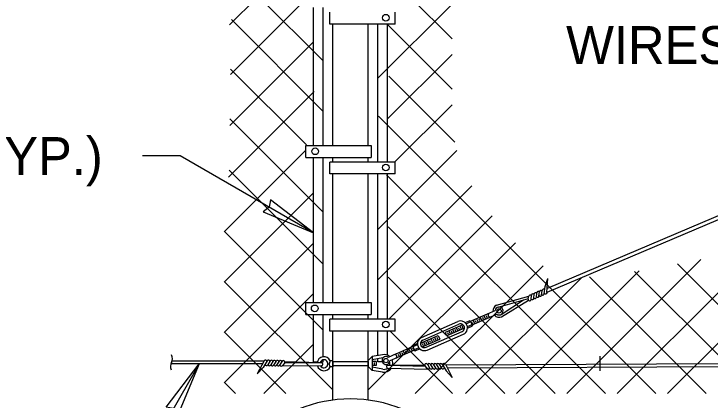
# Model space of a CAD drawing. Extents: x 99862 to 104211, y 98939 to 105076.
# Drawn here: x 100145.4 to 100439.3, y 101282.8 to 101445.9 of the extents above; entities that cross this region are included whole.
import ezdxf

# ---------------------------------------------------------------- set-up
doc = ezdxf.new("R2010")
doc.units = 0
for name, color, linetype in [('Level 15', 7, 'Continuous'), ('Level 2', 7, 'Continuous'), ('Level 20', 7, 'Continuous'), ('Level 4', 7, 'Continuous'), ('Level 6', 7, 'Continuous'), ('Level 7', 7, 'Continuous')]:
    doc.layers.add(name, color=color, linetype=linetype)

msp = doc.modelspace()

# ---------------------------------------------------------------- linework, layer by layer
at = {"layer": 'Level 15'}
for p, q in [((100215.65, 101385.93), (100199.65, 101385.93)), ((100271.94, 101353.42), (100215.65, 101385.92)), ((100223.62, 101298.08), (100191.25, 101242.02))]:
    msp.add_line(p, q, dxfattribs=at)
for points in [[(100271.94, 101353.43), (100253.66, 101367.43), (100253.09, 101364.31), (100250.68, 101362.26)], [(100223.62, 101298.08), (100214.79, 101276.82), (100212.73, 101279.23), (100209.62, 101279.8)]]:
    msp.add_lwpolyline(points, close=True, dxfattribs=at)
at = {"layer": 'Level 2'}
for p, q in [((100960.97, 101579.87), (100370.46, 101328.2)), ((100961.07, 101581.33), (100370.56, 101329.95)), ((100369.67, 101330.79), (100370.8, 101334.2)), ((100370.46, 101328.19), (100370.8, 101334.2)), ((100369.29, 101327.6), (100369.67, 101330.79)), ((100363.75, 101325.22), (100363.97, 101327.14)), ((100364.86, 101325.68), (100365.09, 101327.65)), ((100365.96, 101326.14), (100366.21, 101328.12)), ((100367.07, 101326.6), (100367.33, 101328.68)), ((100368.18, 101327.09), (100368.43, 101329.07)), ((100349.2, 101322.82), (100362.8, 101326.6)), ((100349.79, 101322.02), (100362.61, 101325.65)), ((100351.07, 101318.97), (100360.53, 101325.06)), ((100351.27, 101318), (100362.63, 101325.01)), ((100362.58, 101325.49), (100362.8, 101326.6)), ((100338.21, 101316.05), (100345.32, 101319.17)), ((100343.8, 101318.5), (100344.47, 101316.97)), ((100344.73, 101318.45), (100345.06, 101317.69)), ((100345.32, 101319.17), (100348.58, 101320.59)), ((100345.99, 101317.64), (100349.25, 101319.07)), ((100317.54, 101309.26), (100332.8, 101315.95)), ((100335.88, 101315.48), (100338.05, 101316.43)), ((100338.05, 101316.43), (100339.05, 101314.14)), ((100338.62, 101315.78), (100338.96, 101315.01)), ((100338.88, 101314.52), (100345.99, 101317.64)), ((100339.22, 101316.49), (100339.89, 101314.97)), ((100340.15, 101316.44), (100340.48, 101315.68)), ((100340.75, 101317.16), (100341.42, 101315.63)), ((100341.68, 101317.11), (100342.01, 101316.35)), ((100342.27, 101317.83), (100342.94, 101316.3)), ((100343.2, 101317.78), (100343.54, 101317.02)), ((100318.04, 101308.12), (100333.3, 101314.81)), ((100334.96, 101314.62), (100327.53, 101311.37)), ((100335.63, 101313.1), (100328.2, 101309.84)), ((100330.59, 101312.71), (100331.26, 101311.18)), ((100331.52, 101312.66), (100331.85, 101311.9)), ((100332.11, 101313.38), (100332.78, 101311.85)), ((100333.04, 101313.33), (100333.38, 101312.57)), ((100333.64, 101314.04), (100334.31, 101312.52)), ((100334.57, 101314), (100334.9, 101313.23)), ((100336.88, 101313.19), (100339.05, 101314.14)), ((100317.06, 101306.78), (100324.48, 101310.03)), ((100319.38, 101305.06), (100334.65, 101311.76)), ((100319.88, 101303.92), (100335.16, 101310.62)), ((100322.96, 101309.36), (100323.63, 101307.84)), ((100324.48, 101310.03), (100325.15, 101308.5)), ((100327.53, 101311.37), (100328.2, 101309.84)), ((100328.46, 101311.32), (100328.8, 101310.56)), ((100329.06, 101312.04), (100329.73, 101310.51)), ((100329.99, 101311.99), (100330.33, 101311.23)), ((100315.79, 101306.68), (100313.63, 101305.73)), ((100317.73, 101305.25), (100325.15, 101308.5)), ((100317.78, 101306.64), (100318.12, 101305.88)), ((100318.38, 101307.35), (100319.05, 101305.83)), ((100319.31, 101307.31), (100319.64, 101306.54)), ((100319.9, 101308.02), (100320.57, 101306.5)), ((100320.83, 101307.98), (100321.17, 101307.21)), ((100321.43, 101308.69), (100322.1, 101307.17)), ((100322.36, 101308.65), (100322.7, 101307.88)), ((100323.89, 101309.31), (100324.22, 101308.55)), ((100313.8, 101305.35), (100306.69, 101302.23)), ((100314.47, 101303.82), (100307.36, 101300.71)), ((100309.74, 101303.57), (100310.41, 101302.04)), ((100310.67, 101303.52), (100311.01, 101302.76)), ((100311.27, 101304.24), (100311.94, 101302.71)), ((100312.2, 101304.19), (100312.54, 101303.43)), ((100312.8, 101304.91), (100313.47, 101303.38)), ((100313.63, 101305.73), (100314.63, 101303.44)), ((100313.73, 101304.86), (100314.06, 101304.1)), ((100316.8, 101304.39), (100314.63, 101303.44)), ((100296.62, 101301.14), (100294.94, 101299.46)), ((100300.94, 101301.91), (100296.62, 101301.14)), ((100296.62, 101301.14), (100296.62, 101295.3)), ((100301.12, 101300.67), (100296.62, 101299.8)), ((100306.71, 101302.24), (100303.45, 101300.81)), ((100307.38, 101300.71), (100304.12, 101299.29)), ((100307.62, 101302.18), (100307.96, 101301.42)), ((100308.22, 101302.9), (100308.89, 101301.37)), ((100309.15, 101302.85), (100309.48, 101302.09)), ((100327.66, 101297.65), (100958.91, 101300.79)), ((100250.34, 101298.08), (100211.63, 101298.08)), ((100250.93, 101299.16), (100212.12, 101299.16)), ((100251.01, 101299.32), (100248.06, 101293.84)), ((100252.36, 101299.36), (100250.61, 101296.54)), ((100253.62, 101299.34), (100252.53, 101297.6)), ((100254.88, 101299.32), (100253.81, 101297.63)), ((100256.12, 101299.27), (100255.02, 101297.52)), ((100257.35, 101299.21), (100256.27, 101297.47)), ((100258.59, 101299.16), (100257.54, 101297.46)), ((100259.57, 101298.4), (100258.87, 101297.46)), ((100275.21, 101298.46), (100259.57, 101298.4)), ((100269.95, 101298.6), (100259.73, 101298.87)), ((100275.23, 101298.46), (100269.95, 101298.6)), ((100278.91, 101299.35), (100278.52, 101298.1)), ((100278.91, 101296.85), (100278.52, 101298.1)), ((100279.97, 101298.93), (100279.97, 101297.26)), ((100294.94, 101298.93), (100279.97, 101298.93)), ((100294.94, 101299.05), (100294.94, 101297.39)), ((100294.94, 101298.22), (100294.94, 101297.39)), ((100298.27, 101299.05), (100296.62, 101299.05)), ((100297.44, 101298.64), (100297.44, 101297.8)), ((100298.27, 101299.05), (100298.27, 101297.39)), ((100308.58, 101297.54), (100318.81, 101297.61)), ((100319.96, 101297.88), (100320.97, 101296.16)), ((100321.19, 101297.91), (100322.24, 101296.15)), ((100322.43, 101297.94), (100323.49, 101296.17)), ((100323.66, 101297.97), (100324.79, 101296.11)), ((100324.92, 101297.97), (100325.98, 101296.2)), ((100326.19, 101297.96), (100327.88, 101295.1)), ((100327.54, 101297.89), (100330.38, 101292.36)), ((100328.32, 101296.35), (100958.26, 101299.48)), ((100250.61, 101296.54), (100248.06, 101293.84)), ((100253.72, 101297.49), (100253.72, 101297.49)), ((100275.19, 101297.21), (100258.46, 101297.14)), ((100294.94, 101297.26), (100279.97, 101297.26)), ((100296.62, 101295.3), (100294.94, 101296.99)), ((100298.27, 101297.39), (100296.62, 101297.39)), ((100301.12, 101295.77), (100296.62, 101296.65)), ((100300.94, 101294.53), (100296.62, 101295.3)), ((100303.31, 101297.51), (100308.58, 101297.54)), ((100303.31, 101297.51), (100318.96, 101297.14)), ((100303.32, 101296.26), (100320.05, 101295.86)), ((100318.96, 101297.14), (100319.64, 101296.18)), ((100327.88, 101295.1), (100330.38, 101292.36))]:
    msp.add_line(p, q, dxfattribs=at)
for points in [[(100336.29, 101315.04), (100338.27, 101315.91)], [(100336.84, 101313.79), (100338.82, 101314.66)], [(100315.84, 101306.08), (100313.86, 101305.21)], [(100316.39, 101304.83), (100314.4, 101303.96)], [(100279.97, 101298.93), (100279.97, 101299.35), (100278.91, 101299.35)], [(100294.94, 101299.05), (100294.94, 101299.46)], [(100279.97, 101297.26), (100279.97, 101296.85), (100278.91, 101296.85)], [(100294.94, 101297.39), (100294.94, 101296.99)]]:
    msp.add_lwpolyline(points, dxfattribs=at)
for centre in [(100350.24, 101320.41), (100302.47, 101299.47)]:
    msp.add_circle(centre, 0.916, dxfattribs=at)
for centre, radius, start, end in [((100363.41, 101326.57), 0.605, 28.7661, 176.7144), ((100364.57, 101327.07), 0.605, 36.3421, 173.4693), ((100365.69, 101327.56), 0.605, 35.2689, 175.7258), ((100366.81, 101328.05), 0.605, 36.1699, 172.965), ((100367.59, 101327.24), 0.605, 216.0905, 359.5302), ((100367.92, 101328.53), 0.605, 36.7927, 180.322), ((100368.7, 101327.72), 0.605, 216.1693, 357.792), ((100369.03, 101329), 0.605, 38.1909, 172.8552), ((100369.86, 101328.22), 0.605, 209.8958, 356.7345), ((100363.15, 101325.31), 0.605, 162.4528, 355.3366), ((100364.26, 101325.79), 0.605, 216.3997, 357.0048), ((100365.37, 101326.27), 0.605, 216.3421, 359.0605), ((100366.48, 101326.76), 0.605, 216.2101, 0.322), ((100350.24, 101320.41), 2.63, 113.1749, 184.958), ((100350.24, 101320.41), 1.67, 233.6727, 173.6727), ((100346.44, 101318.75), 0.833, 113.6727, 293.6727), ((100350.24, 101320.41), 2.63, 222.1419, 293.1749), ((100333.97, 101313.28), 2.92, 37.2007, 113.6746), ((100333.97, 101313.28), 1.67, 53.6838, 113.6744), ((100333.97, 101313.28), 1.67, 293.6727, 53.6838), ((100333.97, 101313.28), 2.92, 293.6727, 37.2007), ((100318.71, 101306.59), 2.92, 113.6708, 190.1479), ((100318.71, 101306.59), 1.67, 173.6727, 293.6727), ((100318.71, 101306.59), 1.67, 113.6709, 173.6727), ((100318.71, 101306.59), 2.92, 189.6133, 293.6727), ((100209.12, 101300.26), 3.2, 330, 30), ((100276.27, 101298.1), 2.92, 25.3769, 172.7881), ((100302.47, 101299.47), 1.67, 53.6727, 353.6727), ((100301.6, 101298.22), 3.75, 49.4316, 100.1113), ((100301.6, 101298.22), 2.5, 95.7425, 101.0207), ((100306.26, 101301.13), 0.833, 293.6727, 113.6727), ((100214.66, 101297.06), 3.2, 150, 206.9934), ((100251.56, 101299.02), 0.625, 4.8632, 151.7019), ((100252, 101297.94), 0.625, 193.1646, 327.8289), ((100252.86, 101298.99), 0.625, 11.143, 143.5923), ((100253.24, 101297.89), 0.625, 191.7664, 335.2957), ((100254.11, 101298.95), 0.625, 154.3668, 154.5039), ((100254.11, 101298.95), 0.625, 11.0642, 141.1539), ((100254.49, 101297.86), 0.625, 191.1436, 327.9387), ((100255.36, 101298.92), 0.625, 11.1838, 139.9368), ((100255.76, 101297.82), 0.625, 190.2426, 325.8817), ((100256.61, 101298.89), 0.625, 153.8022, 154.0342), ((100256.61, 101298.89), 0.625, 11.3158, 141.8431), ((100257.01, 101297.79), 0.625, 191.3158, 328.443), ((100257.86, 101298.85), 0.625, 11.3734, 144.6027), ((100258.32, 101297.75), 0.625, 183.7398, 331.6881), ((100259.11, 101298.82), 0.625, 150.1377, 150.3103), ((100259.11, 101298.82), 0.625, 317.4265, 146.5757), ((100276.27, 101298.1), 1.67, 41.9482, 167.4497), ((100276.27, 101298.1), 1.67, 212.6493, 41.9482), ((100275.21, 101297.83), 0.625, 268.4659, 90.2119), ((100301.6, 101298.22), 2.5, 343.3732, 14.8434), ((100301.6, 101298.22), 3.75, 349.003, 23.1078), ((100319.43, 101297.55), 0.625, 28.5603, 221.4441), ((100320.68, 101297.56), 0.625, 26.8921, 167.4972), ((100321.93, 101297.57), 0.625, 24.8364, 167.5548), ((100323.18, 101297.58), 0.625, 23.5749, 167.6867), ((100324.43, 101297.59), 0.625, 24.3666, 167.8064), ((100325.68, 101297.59), 0.625, 26.1049, 167.7276), ((100326.98, 101297.6), 0.625, 27.1624, 174.0011), ((100276.27, 101298.1), 2.92, 198.7243, 334.6231), ((100301.6, 101298.22), 3.75, 259.8887, 327.5882), ((100301.6, 101298.22), 2.5, 258.8638, 308.7888), ((100303.31, 101296.88), 0.625, 90.4046, 270.4046), ((100320.2, 101296.47), 0.625, 207.1825, 355.1307), ((100321.51, 101296.48), 0.625, 210.4276, 347.5548), ((100322.76, 101296.49), 0.625, 208.1711, 348.628), ((100324.03, 101296.5), 0.625, 210.9319, 347.727), ((100325.28, 101296.51), 0.625, 203.5749, 347.1042), ((100326.52, 101296.53), 0.625, 211.0417, 345.706)]:
    msp.add_arc(centre, radius, start, end, dxfattribs=at)
at = {"layer": 'Level 4'}
for p, q in [((100236.47, 101441.29), (100271.77, 101476.59)), ((100275.96, 101426.04), (100235.97, 101466.03)), ((100330.41, 101435.42), (100303.25, 101462.57)), ((100236.84, 101420.38), (100269.94, 101453.48)), ((100299.03, 101418.73), (100330.41, 101450.1)), ((100275.96, 101404.75), (100237.19, 101443.53)), ((100330.41, 101414.14), (100303.08, 101441.47)), ((100236.52, 101398.79), (100271.77, 101434.03)), ((100302.96, 101401.41), (100330.41, 101428.84)), ((100268.9, 101390.54), (100236.88, 101422.55)), ((100331.55, 101391.72), (100303.62, 101419.65)), ((100235.99, 101377), (100272.13, 101413.13)), ((100306.24, 101383.38), (100330.41, 101407.55)), ((100275.96, 101362.2), (100236.57, 101401.59)), ((100416.43, 101285.55), (100299.34, 101402.66)), ((100234.15, 101353.85), (100268.66, 101388.36)), ((100299.03, 101354.9), (100332.39, 101388.26)), ((100275.96, 101340.13), (100236.22, 101379.87)), ((100395.16, 101285.55), (100302.73, 101377.98)), ((100299.03, 101333.63), (100338.71, 101373.3)), ((100234.15, 101332.64), (100271.56, 101370.03)), ((100303.67, 101316.98), (100347.3, 101360.61)), ((100275.96, 101312.37), (100234.17, 101354.16)), ((100373.88, 101285.55), (100303.41, 101356.02)), ((100421.38, 101285.55), (100486.76, 101350.93)), ((100234.15, 101311.3), (100271.89, 101349.03)), ((100295.02, 101287.05), (100357.17, 101349.19)), ((100400.1, 101285.55), (100461.82, 101347.27)), ((100378.82, 101285.55), (100435.46, 101342.19)), ((100314.79, 101285.55), (100368.8, 101339.55)), ((100480.27, 101285.55), (100425.56, 101340.26)), ((100357.55, 101285.55), (100409.4, 101337.41)), ((100459, 101285.55), (100407.44, 101337.11)), ((100279.97, 101287.08), (100234.15, 101332.9)), ((100352.61, 101285.55), (100303.43, 101334.72)), ((100336.1, 101285.55), (100385.14, 101334.59)), ((100437.72, 101285.55), (100388.46, 101334.8)), ((100234.15, 101290.02), (100271.93, 101327.8)), ((100260.23, 101285.55), (100234.15, 101311.63)), ((100330.54, 101285.55), (100304.13, 101311.96)), ((100250.95, 101285.55), (100271.84, 101306.44)), ((100392.77, 101301.3), (100392.77, 101295.16)), ((100238.92, 101285.55), (100234.15, 101290.32))]:
    msp.add_line(p, q, dxfattribs=at)
at = {"layer": 'Level 6'}
msp.add_arc((100287.51, 101226.19), 57.06, 67.3801, 112.6199, dxfattribs=at)
at = {"layer": 'Level 7'}
for p, q in [((100271.94, 101390.33), (100271.94, 101448.61)), ((100275.96, 101390.33), (100275.96, 101448.61)), ((100278.72, 101441.6), (100278.72, 101446.61)), ((100306.3, 101441.6), (100306.3, 101446.61)), ((100306.3, 101441.6), (100278.72, 101441.6)), ((100279.97, 101431.49), (100279.97, 101441.6)), ((100295.02, 101431.49), (100295.02, 101441.6)), ((100299.03, 101383.31), (100299.03, 101441.6)), ((100303.05, 101383.31), (100303.05, 101441.6)), ((100279.97, 101390.33), (100279.97, 101431.49)), ((100295.02, 101390.33), (100295.02, 101431.49)), ((100268.69, 101390.33), (100296.27, 101390.33)), ((100268.69, 101385.31), (100268.69, 101390.33)), ((100296.27, 101390.33), (100296.27, 101385.31)), ((100268.69, 101385.31), (100296.27, 101385.31)), ((100271.94, 101323.97), (100271.94, 101385.31)), ((100275.96, 101323.97), (100275.96, 101385.31)), ((100306.3, 101383.31), (100278.72, 101383.31)), ((100278.72, 101378.3), (100278.72, 101383.31)), ((100279.97, 101383.31), (100279.97, 101385.31)), ((100295.02, 101383.31), (100295.02, 101385.31)), ((100306.3, 101378.3), (100306.3, 101383.31)), ((100306.3, 101378.3), (100278.72, 101378.3)), ((100279.97, 101323.97), (100279.97, 101378.3)), ((100295.02, 101323.97), (100295.02, 101378.3)), ((100295.02, 101358.52), (100295.02, 101378.3)), ((100299.03, 101316.96), (100299.03, 101378.3)), ((100303.05, 101316.96), (100303.05, 101378.3)), ((100268.69, 101323.97), (100296.27, 101323.97)), ((100268.69, 101318.96), (100268.69, 101323.97)), ((100296.27, 101323.97), (100296.27, 101318.96)), ((100268.69, 101318.96), (100296.27, 101318.96)), ((100271.94, 101298.87), (100271.94, 101318.96)), ((100275.96, 101300.99), (100275.96, 101318.96)), ((100279.97, 101316.96), (100279.97, 101318.96)), ((100295.02, 101316.96), (100295.02, 101318.96)), ((100306.3, 101316.96), (100278.72, 101316.96)), ((100278.72, 101311.94), (100278.72, 101316.96)), ((100306.3, 101311.94), (100306.3, 101316.96)), ((100306.3, 101311.94), (100278.72, 101311.94)), ((100279.97, 101282.79), (100279.97, 101311.94)), ((100295.02, 101282.79), (100295.02, 101311.94)), ((100299.03, 101301.57), (100299.03, 101311.94)), ((100303.05, 101301.68), (100303.05, 101311.94)), ((100271.94, 101298.87), (100273.46, 101298.87)), ((100274.8, 101298.87), (100275.96, 101298.87)), ((100275.96, 101298.87), (100275.96, 101299.73)), ((100299.03, 101298.87), (100299.03, 101300.27)), ((100300.91, 101298.87), (100299.03, 101298.87))]:
    msp.add_line(p, q, dxfattribs=at)
for centre in [(100302.41, 101444.31), (100272.58, 101387.87), (100302.41, 101381.01), (100272.4, 101321.52), (100302.41, 101314.66)]:
    msp.add_circle(centre, 1.41, dxfattribs=at)

# ---------------------------------------------------------------- texts
at = {"layer": 'Level 20'}
msp.add_text('WIRES', height=16, dxfattribs=at).set_placement((100378.52, 101424.79))
msp.add_text('STRETCHER BAR (TYP.)', height=16, rotation=360, dxfattribs=at).set_placement((99934.46, 101377.88))

doc.saveas('drawing.dxf')
